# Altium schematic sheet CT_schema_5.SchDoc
size 208 x 258 mm
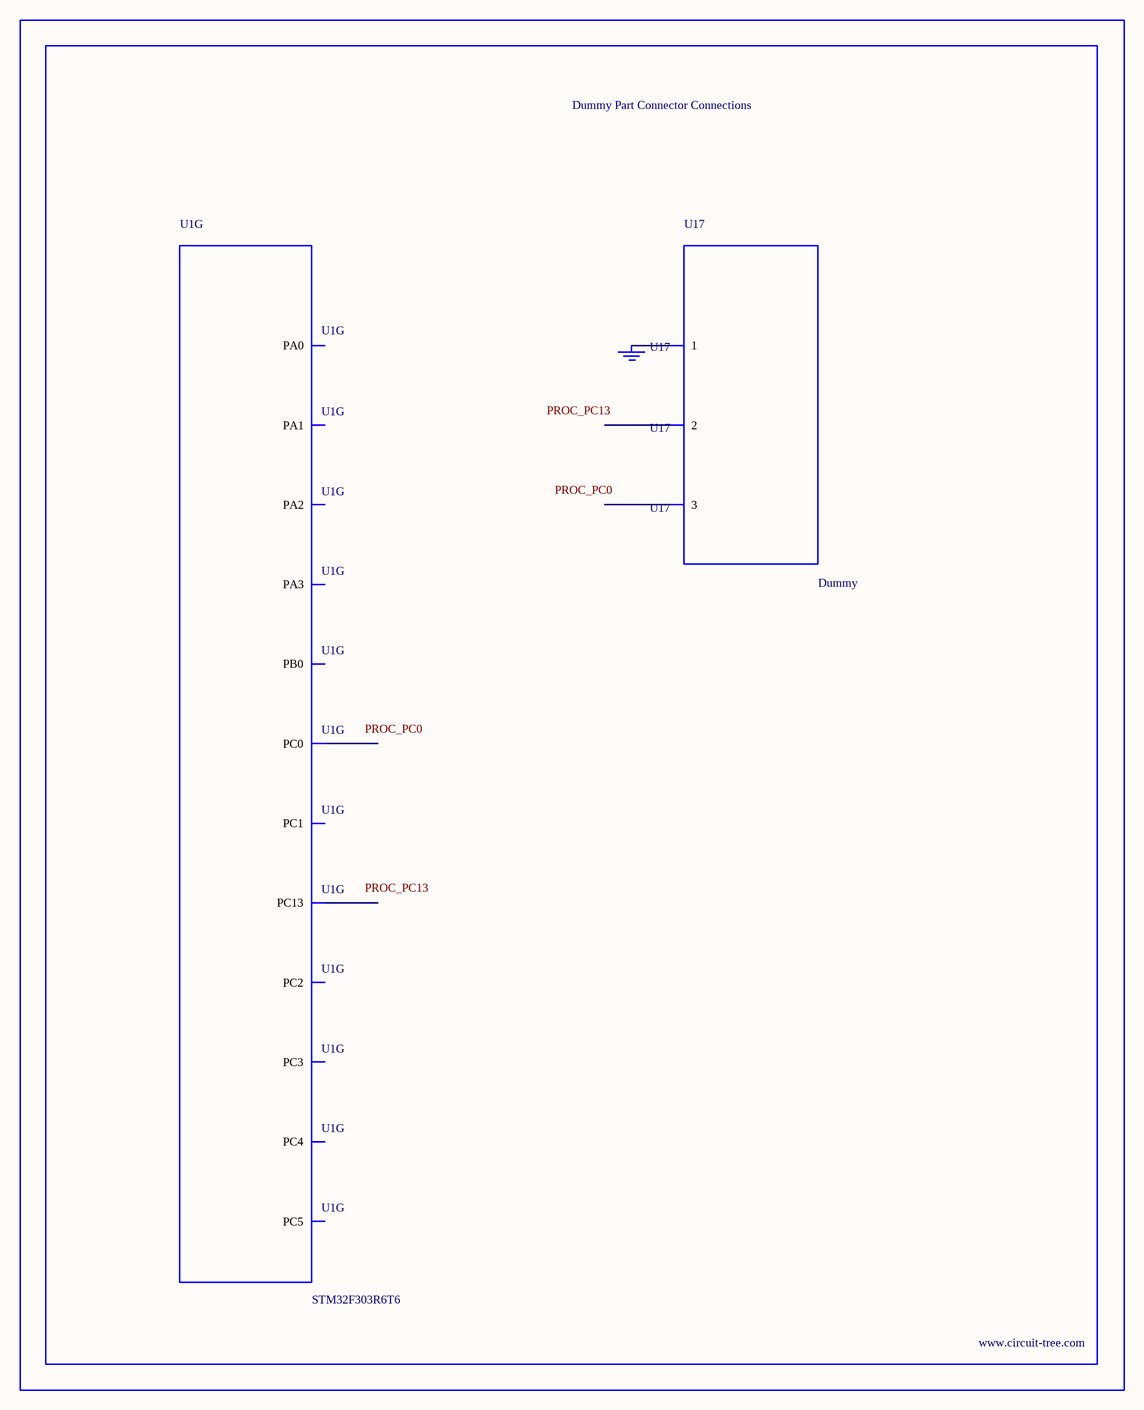
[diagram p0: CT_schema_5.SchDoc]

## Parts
BORDER4  (no value)
GND_INSTANCE_4_0  (no value)
U1  STM32F303R6T6  [LQFP64]  (part G of 7)
U17  Dummy  [DUMMY_PACKAGE_135]

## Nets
NetGND_INSTANCE_4_0_0: GND_INSTANCE_4_0.0(GND) U17.1

Not connected (* = marked no-connect by the designer): U1 2(PC13) 8(PC0) 9(PC1) 10(PC2) 11(PC3) 14(PA0) 15(PA1) 16(PA2) 17(PA3) 24(PC4) 25(PC5) 26(PB0); U17 2 3

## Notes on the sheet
- Labels drawn without touching a wire or pin: PROC_PC0, PROC_PC13

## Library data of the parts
BORDER4 = BORDER_PAGE4
GND_INSTANCE_4_0 = GND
